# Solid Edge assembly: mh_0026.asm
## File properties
Title: cover_unuit
Author: edge
Template: normal.asm
Last saved by: edge
Revision: 30
Application: Solid Edge
文書内容のタイプ: 1
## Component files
mh_0027.par
mh_0028.par
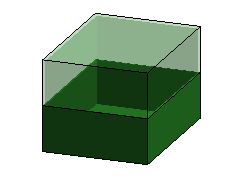
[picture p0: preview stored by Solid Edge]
